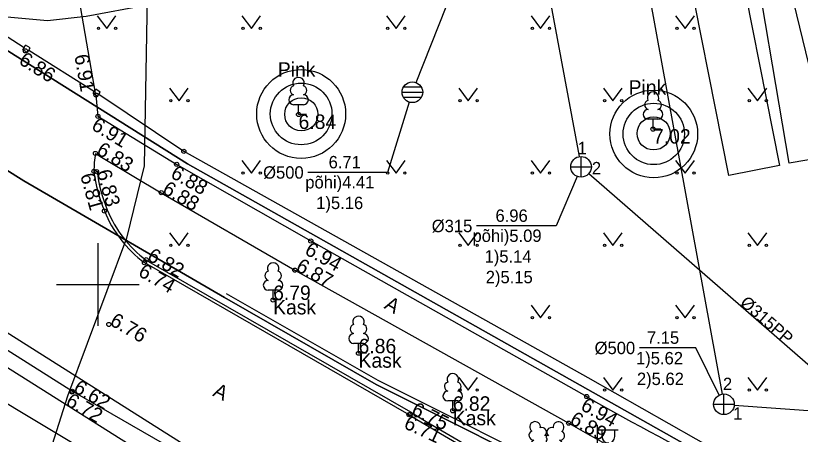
# Model space of a CAD drawing. Extents: x 473307 to 473719, y 6532843 to 6533381.
# Drawn here: x 473546.03 to 473584.01, y 6532942.76 to 6532963.02 of the extents above; entities that cross this region are included whole.
import ezdxf

# ---------------------------------------------------------------- set-up
doc = ezdxf.new("R2010")
doc.units = 0
for name, color, linetype in [('AED', 7, 'Continuous'), ('Default', 7, 'Continuous'), ('HALJASTUS', 7, 'Continuous'), ('KKAEV', 7, 'Continuous'), ('KKAEV_NR', 7, 'Continuous'), ('KORGUS', 7, 'Continuous'), ('KPKAABEL', 7, 'Continuous'), ('KTRASS', 7, 'Continuous'), ('MPKAABEL', 7, 'Continuous'), ('MPOHULIIN', 7, 'Continuous'), ('PIIR', 7, 'Continuous'), ('POST', 7, 'Continuous'), ('PUU', 7, 'Continuous'), ('RAJATIS', 7, 'Continuous'), ('SKKAEV', 7, 'Continuous'), ('SKKAEV_NR', 7, 'Continuous'), ('SKTRASS', 7, 'Continuous'), ('SKTRASS_TEKST', 7, 'Continuous'), ('TEE', 7, 'Continuous'), ('VORK', 7, 'Continuous'), ('VTRASS', 7, 'Continuous')]:
    doc.layers.add(name, color=color, linetype=linetype)

# ---------------------------------------------------------------- blocks, each defined once
blk = doc.blocks.new('KAKAEV')
at = {"layer": 'Default'}
for p, q in [((0, -1), (0, 1)), ((-1, 0), (1, 0))]:
    blk.add_line(p, q, dxfattribs=at)
blk.add_circle((0, 0), 1, dxfattribs=at)
blk = doc.blocks.new('LEHTP1')
at = {"layer": 'Default'}
for p, q in [((0.48, 0.95), (-0.48, 0.95)), ((0, 0), (0, 0.95)), ((0.76, 0), (0, 0))]:
    blk.add_line(p, q, dxfattribs=at)
for centre, radius, start, end in [((0, 3.04), 0.554, 332.5799, 207.4201), ((-0.34, 2.345), 0.465, 109.02174, 253.14154), ((0.34, 2.345), 0.465, 286.85082, 70.98591), ((-0.475, 1.425), 0.475, 90.0016, 269.3953), ((0.475, 1.425), 0.475, 270.6047, 89.9984)]:
    blk.add_arc(centre, radius, start, end, dxfattribs=at)
blk = doc.blocks.new('VAPOST')
at = {"layer": 'Default'}
for p, q in [((0, 0.5), (0, 4.5)), ((0, 4), (2, 4)), ((0.453, 3.358), (0.453, 4)), ((1.679, 3.358), (1.679, 4))]:
    blk.add_line(p, q, dxfattribs=at)
blk.add_arc((1.066, 3.358), 0.613, 180, 0, dxfattribs=at)
blk = doc.blocks.new('LEHTP2')
at = {"layer": 'Default'}
for p, q in [((-0.88, 0.67), (0.01, 1.02)), ((0, 0), (-0.35, 0.88)), ((0, 0), (0.36, 0.88)), ((0.01, 1.02), (0.89, 0.66)), ((0.76, 0), (0, 0))]:
    blk.add_line(p, q, dxfattribs=at)
blk.add_lwpolyline([(0.01, 2.01), (-0.03, 1.86), (-0.03, 1.82), (-0.01, 1.76), (0.03, 1.69), (0.04, 1.65), (0.01, 1.58), (-0.04, 1.48), (-0.05, 1.43), (-0.04, 1.4), (-0.02, 1.34), (0.05, 1.22), (0.06, 1.18), (0.05, 1.14), (0.02, 1.07), (0.01, 1.02)], dxfattribs=at)
for centre, radius, start, end in [((-1.114, 2.828), 0.512, 111.50269, 232.51731), ((-1.114, 2.828), 0.512, 350.48556, 111.50017), ((1.158, 2.811), 0.512, 67.6168, 188.63142), ((1.158, 2.811), 0.512, 306.59966, 67.61428), ((-1.262, 2.005), 0.448, 111.43041, 274.49868), ((-0.445, 2.327), 0.448, 308.50412, 111.57247), ((0.481, 2.318), 0.45, 67.7016, 230.51262), ((1.293, 1.986), 0.448, 264.6183, 67.68657), ((-1.053, 1.117), 0.475, 111.50143, 291.50036), ((0.008, 1.535), 0.475, 66.76552, 111.50149), ((1.07, 1.101), 0.475, 247.61661, 67.61554)]:
    blk.add_arc(centre, radius, start, end, dxfattribs=at)
blk = doc.blocks.new('VARPOS')
at = {"layer": 'Default'}
for p, q in [((-0.25, 0.25), (-0.25, -0.25)), ((-0.25, 0.25), (0.25, 0.25)), ((0.25, 0.25), (0.25, -0.25)), ((-0.25, -0.25), (0.25, -0.25))]:
    blk.add_line(p, q, dxfattribs=at)
blk = doc.blocks.new('REKAEV')
at = {"layer": 'Default'}
for p, q in [((-1, 0), (1, 0)), ((0.86, 0.5), (-0.86, 0.5)), ((0.86, -0.5), (-0.86, -0.5))]:
    blk.add_line(p, q, dxfattribs=at)
blk.add_circle((0, 0), 1, dxfattribs=at)
blk = doc.blocks.new('MURU')
at = {"layer": 'Default'}
for p, q in [((-0.927, 1.213), (0, 0)), ((0, 0), (0.891, 1.213))]:
    blk.add_line(p, q, dxfattribs=at)
for centre in [(-0.802, 0), (0.856, 0)]:
    blk.add_circle(centre, 0.11, dxfattribs=at)
blk = doc.blocks.new('VKORIS')
at = {"layer": 'Default'}
for p, q in [((0, 4), (0, -4)), ((-4, 0), (4, 0))]:
    blk.add_line(p, q, dxfattribs=at)

msp = doc.modelspace()

# ---------------------------------------------------------------- linework, layer by layer
at = {"layer": 'AED'}
for points in [[(473531.197, 6532971.332), (473546.442, 6532961.469)], [(473546.66, 6532961.347), (473549.841, 6532959.348)], [(473550.051, 6532959.211), (473554.174, 6532956.453), (473573.719, 6532945.513), (473580.254, 6532941.8), (473591.86, 6532937.524), (473605.919, 6532932.298), (473608.286, 6532931.42), (473621.231, 6532928.229), (473637.541, 6532925.082), (473652.528, 6532925.143), (473654.3, 6532926.84), (473651.933, 6532941.676), (473648.983, 6532959.55), (473630.652, 6532956.493)]]:
    msp.add_lwpolyline(points, dxfattribs=at)
at = {"layer": 'KKAEV_NR'}
msp.add_lwpolyline([(473580.087, 6532944.655), (473578.944, 6532946.937), (473576.223, 6532946.937)], dxfattribs=at)
at = {"layer": 'KORGUS'}
for centre in [(473546.5, 6532961.312), (473549.913, 6532959.174), (473550.008, 6532958.145), (473559.72, 6532958.233), (473576.879, 6532957.526), (473549.889, 6532956.35), (473554.167, 6532956.453), (473553.823, 6532955.821), (473549.817, 6532955.48), (473549.942, 6532955.467), (473553.076, 6532954.45), (473550.323, 6532953.564), (473560.312, 6532952.113), (473552.344, 6532951.212), (473552.259, 6532951.064), (473559.541, 6532950.703), (473558.489, 6532949.258), (473558.489, 6532949.258), (473550.537, 6532948.074), (473550.537, 6532948.074), (473562.625, 6532946.679), (473562.625, 6532946.679), (473548.754, 6532944.802), (473548.754, 6532944.802), (473548.771, 6532944.84), (473548.771, 6532944.84), (473573.67, 6532944.583), (473565.065, 6532943.709), (473565.065, 6532943.709), (473565.128, 6532943.726), (473565.128, 6532943.726), (473567.185, 6532943.895), (473567.185, 6532943.895), (473572.797, 6532943.295)]:
    msp.add_circle(centre, 0.1, dxfattribs=at)
at = {"layer": 'KPKAABEL'}
msp.add_lwpolyline([(473552.428, 6532965.743), (473552.248, 6532955.743), (473551.396, 6532952.25), (473548.538, 6532944.595), (473546.922, 6532939.52), (473555.37, 6532934.798), (473562.977, 6532930.797), (473573.936, 6532926.157), (473585.002, 6532921.176), (473597.713, 6532916.33), (473608.101, 6532913.364), (473620.133, 6532910.115), (473635.44, 6532908.143), (473647.319, 6532907.126), (473658.175, 6532907.682), (473669.898, 6532907.954), (473678.245, 6532908.166), (473679.837, 6532908.723), (473681.3, 6532908.756), (473682.619, 6532907.437), (473683.14, 6532903.797)], dxfattribs=at)
at = {"layer": 'KTRASS'}
msp.add_line((473505.335, 6532971.329), (473560.125, 6532936.877), dxfattribs=at)
for points in [[(473573.778, 6532980.035), (473580.221, 6532944.7)], [(473580.81, 6532944.172), (473634.611, 6532940.293)]]:
    msp.add_lwpolyline(points, dxfattribs=at)
at = {"layer": 'MPKAABEL'}
for points in [[(473592.161, 6532931.655), (473583.871, 6532934.989), (473574.572, 6532939.314), (473574.03, 6532940.034), (473574.304, 6532941.029), (473573.472, 6532940.172), (473563.473, 6532945.174), (473556.129, 6532949.371), (473546.422, 6532955.029), (473536.136, 6532961.464), (473535.978, 6532962.869), (473534.663, 6532962.568), (473525.661, 6532968.571), (473517.097, 6532975.071), (473509.151, 6532981.519), (473503.051, 6532987.775), (473502.694, 6532988.631), (473501.293, 6532988.874), (473494.528, 6532995.717), (473488.455, 6533001.872), (473481.096, 6533010.082), (473475.299, 6533017.476)], [(473493.252, 6532975.715), (473497.24, 6532978.112), (473498.183, 6532979.06), (473499.269, 6532980.163), (473501.448, 6532982.423), (473503.504, 6532984.545), (473505.843, 6532986.884), (473507.45, 6532987.966), (473517.665, 6532979.32), (473529.752, 6532970.098), (473534.316, 6532966.914), (473541.139, 6532963.364), (473547.56, 6532962.777), (473549.436, 6532962.995), (473552.396, 6532963.548), (473552.501, 6532963.798), (473552.517, 6532963.893), (473552.555, 6532965.764)], [(473583.229, 6532977.274), (473582.388, 6532976.276), (473581.518, 6532974.611), (473581.518, 6532974.611), (473581.55, 6532974.485), (473581.806, 6532974.382), (473582.092, 6532971.765), (473582.897, 6532967.472), (473583.344, 6532967.218), (473583.499, 6532966.399), (473583.498, 6532965.835), (473583.235, 6532965.46), (473587.471, 6532948.068)], [(473535.978, 6532962.869), (473536.136, 6532961.464), (473546.422, 6532955.029), (473556.129, 6532949.371), (473563.473, 6532945.174), (473573.472, 6532940.172), (473574.304, 6532941.029)], [(473574.304, 6532941.029), (473573.428, 6532940.429), (473563.572, 6532945.359), (473556.234, 6532949.553)]]:
    msp.add_lwpolyline(points, dxfattribs=at)
at = {"layer": 'MPOHULIIN'}
msp.add_lwpolyline([(473423.194, 6533272.897), (473391.791, 6533270.484), (473361.09, 6533267.919), (473364.229, 6533220.925), (473380.477, 6533175.317), (473396.165, 6533131.758), (473413.567, 6533083.532), (473430.968, 6533052.6), (473459.84, 6533016.944), (473493.252, 6532975.715), (473524.159, 6532957.128), (473561.498, 6532934.712), (473599.705, 6532914.54), (473648.184, 6532910.183)], dxfattribs=at)
at = {"layer": 'PIIR'}
msp.add_lwpolyline([(473486.57, 6533007.64), (473478.82, 6533017), (473548.5, 6533028.91), (473572.63, 6533056.43), (473618.6, 6533063.82), (473630.89, 6533065.72), (473654.16, 6532926.37), (473652.82, 6532924.82), (473637.7, 6532924.6), (473625.07, 6532926.73), (473607.63, 6532930.98), (473579.04, 6532941.93), (473554.34, 6532955.84), (473531.51, 6532970.21), (473509.62, 6532987.09)], close=True, dxfattribs=at)
msp.add_lwpolyline([(473455.33, 6533045.76), (473478.82, 6533017), (473486.57, 6533007.64), (473509.62, 6532987.09), (473531.51, 6532970.21), (473554.34, 6532955.84), (473579.04, 6532941.93), (473607.63, 6532930.98), (473625.07, 6532926.73), (473637.7, 6532924.6), (473652.82, 6532924.82), (473654.16, 6532926.37), (473664.64, 6532927.81), (473668.24, 6532906.4), (473641.69, 6532906.33), (473620.6, 6532909.02), (473600.1, 6532914.5), (473579.89, 6532922.16), (473559.95, 6532931.3), (473540.88, 6532942.28), (473521.95, 6532954.78), (473501.05, 6532969.5), (473492.55, 6532977.62), (473473.12, 6532997.79)], dxfattribs=at)
at = {"layer": 'RAJATIS'}
for centre, radius in [((473559.846, 6532958.26), 2.151), ((473559.846, 6532958.26), 1.492), ((473576.915, 6532957.292), 2.122), ((473559.853, 6532958.242), 0.804), ((473576.915, 6532957.292), 1.485), ((473576.909, 6532957.317), 0.8)]:
    msp.add_circle(centre, radius, dxfattribs=at)
at = {"layer": 'SKKAEV_NR'}
for points in [[(473565.081, 6532958.833), (473564.031, 6532955.428), (473560.176, 6532955.428)], [(473573.2, 6532955.241), (473572.195, 6532952.839), (473568.34, 6532952.839)]]:
    msp.add_lwpolyline(points, dxfattribs=at)
at = {"layer": 'SKTRASS'}
for points in [[(473565.412, 6532959.776), (473570.144, 6532971.727)], [(473570.419, 6532971.7), (473573.302, 6532956.194)], [(473573.77, 6532955.374), (473585.614, 6532945.077)]]:
    msp.add_lwpolyline(points, dxfattribs=at)
at = {"layer": 'TEE'}
msp.add_line((473549.686, 6532956.116), (473549.686, 6532956.116), dxfattribs=at)
for points in [[(473507.269, 6532973.243), (473516.735, 6532966.211), (473521.977, 6532962.129), (473526.063, 6532959.019), (473526.41, 6532958.663), (473523.968, 6532954.435), (473525.686, 6532952.96), (473528.95, 6532956.691), (473529.581, 6532956.846), (473534.188, 6532954.059), (473548.771, 6532944.84), (473558.935, 6532938.993), (473557.576, 6532936.09)], [(473549.913, 6532959.174), (473548.867, 6532965.152)], [(473549.913, 6532959.174), (473550.008, 6532958.145), (473553.823, 6532955.821), (473560.312, 6532952.113), (473573.67, 6532944.583)], [(473549.889, 6532956.35), (473550.345, 6532956.077), (473553.076, 6532954.45), (473559.541, 6532950.703), (473572.797, 6532943.295)], [(473552.259, 6532951.064), (473565.065, 6532943.709)], [(473552.341, 6532951.19), (473565.141, 6532943.838)]]:
    msp.add_lwpolyline(points, dxfattribs=at)
for centre, radius, start, end in [((473554.404, 6532955.538), 4.587, 169.8089, 180.7293), ((473556.992, 6532956.35), 7.228, 186.9144, 202.6728), ((473556.992, 6532956.35), 7.078, 186.9144, 202.6792), ((473555.741, 6532955.76), 5.697, 202.0573, 233.3555), ((473555.741, 6532955.76), 5.847, 202.0653, 233.4431), ((473627.25, 6533037.149), 106.955, 239.93646, 244.18867), ((473649.986, 6533084.531), 164.445, 238.90844, 243.87641), ((473649.986, 6533084.531), 164.295, 238.90789, 243.87579), ((473627.795, 6533039.271), 110.617, 240.18538, 244.53648)]:
    msp.add_arc(centre, radius, start, end, dxfattribs=at)
at = {"layer": 'VTRASS'}
msp.add_lwpolyline([(473503.731, 6532976.927), (473535.265, 6532954.21), (473555.891, 6532941.175), (473565.122, 6532936.508), (473600.672, 6532921.587), (473636.512, 6532914.617), (473674.923, 6532915.363), (473675.557, 6532915.427)], dxfattribs=at)
for points in [[(473585.934, 6532956.295), (473583.47, 6532955.877), (473581.516, 6532967.408), (473583.98, 6532967.826)], [(473580.727, 6532967.275), (473582.995, 6532955.767), (473580.543, 6532955.283), (473578.275, 6532966.791)]]:
    msp.add_lwpolyline(points, close=True, dxfattribs=at)

# ---------------------------------------------------------------- block references
at = {"layer": 'AED', "xscale": 0.5}
for p, yscale, rotation in [((473546.553, 6532961.411), 0.5, 148.96420870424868), ((473549.947, 6532959.281), 0.49999999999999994, 147.720314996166)]:
    msp.add_blockref('VARPOS', p, dxfattribs=dict(at, yscale=yscale, rotation=rotation))
at = {"layer": 'HALJASTUS', "xscale": 0.5, "yscale": 0.5}
for p in [(473550.438, 6532962.399), (473557.438, 6532962.399), (473564.438, 6532962.399), (473571.438, 6532962.399), (473578.438, 6532962.399), (473553.938, 6532958.899), (473567.938, 6532958.899), (473574.938, 6532958.899), (473581.938, 6532958.899), (473557.438, 6532955.399), (473564.438, 6532955.399), (473571.438, 6532955.399), (473578.438, 6532955.399), (473553.938, 6532951.899), (473567.938, 6532951.899), (473574.938, 6532951.899), (473581.938, 6532951.899), (473571.438, 6532948.399), (473578.438, 6532948.399), (473567.938, 6532944.899), (473574.938, 6532944.899), (473581.938, 6532944.899)]:
    msp.add_blockref('MURU', p, dxfattribs=at)
at = {"layer": 'KKAEV', "xscale": 0.5, "yscale": 0.5}
msp.add_blockref('KAKAEV', (473580.311, 6532944.208), dxfattribs=at)
at = {"layer": 'POST', "xscale": 0.5, "yscale": 0.5}
msp.add_blockref('VAPOST', (473574.186, 6532940.966), dxfattribs=at)
at = {"layer": 'PUU', "xscale": 0.5, "yscale": 0.5}
for name, p in [('LEHTP1', (473559.72, 6532958.233)), ('LEHTP1', (473576.879, 6532957.526)), ('LEHTP1', (473558.489, 6532949.258)), ('LEHTP1', (473562.625, 6532946.679)), ('LEHTP1', (473567.185, 6532943.895)), ('LEHTP2', (473571.726, 6532941.7))]:
    msp.add_blockref(name, p, dxfattribs=at)
at = {"layer": 'SKKAEV', "xscale": 0.5, "yscale": 0.5}
for name, p in [('REKAEV', (473565.228, 6532959.311)), ('KAKAEV', (473573.393, 6532955.702))]:
    msp.add_blockref(name, p, dxfattribs=at)
at = {"layer": 'VORK', "xscale": 0.5, "yscale": 0.5}
msp.add_blockref('VKORIS', (473550, 6532950), dxfattribs=at)

# ---------------------------------------------------------------- texts
at = {"layer": 'KKAEV_NR'}
for s, p in [('7.15', (473576.583, 6532947.137)), ('%%C500', (473574.051, 6532946.637)), ('1)5.62', (473576.055, 6532946.141)), ('2)5.62', (473576.098, 6532945.141)), ('2', (473580.262, 6532944.896)), ('1', (473580.759, 6532943.462))]:
    msp.add_text(s, height=0.6, dxfattribs=at).set_placement(p)
at = {"layer": 'KORGUS'}
for s, rotation, p in [('6.86', 327.8583, (473546.128, 6532960.719)), ('6.91', 279.9249, (473548.867, 6532961.089)), ('6.91', 328.6513, (473549.644, 6532957.547)), ('6.83', 329.1461, (473549.889, 6532956.35)), ('6.83', 285.714, (473549.942, 6532955.467)), ('6.88', 330.2551, (473553.476, 6532955.213)), ('6.81', 285.714, (473549.143, 6532955.29)), ('6.88', 329.9042, (473553.076, 6532954.45)), ('6.82', 330.1968, (473552.344, 6532951.212)), ('6.94', 330.5897, (473559.968, 6532951.503)), ('6.74', 330.1968, (473551.911, 6532950.457)), ('6.87', 330.8017, (473559.541, 6532950.703)), ('6.76', 329.897, (473550.537, 6532948.074)), ('6.62', 329.7497, (473548.771, 6532944.84)), ('6.72', 329.7497, (473548.401, 6532944.197)), ('6.94', 330.5157, (473573.325, 6532943.974)), ('6.75', 333.8392, (473565.128, 6532943.726)), ('6.89', 330.7726, (473572.797, 6532943.295)), ('6.71', 335.0102, (473564.769, 6532943.075))]:
    msp.add_text(s, height=0.7, rotation=rotation, dxfattribs=at).set_placement(p)
for s, p in [('6.84', (473559.72, 6532957.533)), ('7.02', (473576.879, 6532956.826)), ('6.79', (473558.489, 6532949.258)), ('6.86', (473562.625, 6532946.679)), ('6.82', (473567.185, 6532943.895))]:
    msp.add_text(s, height=0.7, dxfattribs=at).set_placement(p)
at = {"layer": 'PUU'}
for p in [(473558.489, 6532948.558), (473562.625, 6532945.979), (473567.185, 6532943.195)]:
    msp.add_text('Kask', height=0.7, dxfattribs=at).set_placement(p)
at = {"layer": 'RAJATIS'}
for p in [(473558.716, 6532960.062), (473575.696, 6532959.194)]:
    msp.add_text('Pink', height=0.7, dxfattribs=at).set_placement(p)
at = {"layer": 'SKKAEV_NR'}
for s, p in [('1', (473573.229, 6532956.311)), ('6.71', (473561.175, 6532955.628)), ('2', (473573.918, 6532955.337)), ('%%C500', (473558.005, 6532955.128)), ('põhi)4.41', (473560.046, 6532954.656)), ('1)5.16', (473560.575, 6532953.656)), ('6.96', (473569.253, 6532953.039)), ('%%C315', (473566.168, 6532952.539)), ('põhi)5.09', (473568.139, 6532952.067)), ('1)5.14', (473568.725, 6532951.067)), ('2)5.15', (473568.782, 6532950.067))]:
    msp.add_text(s, height=0.6, dxfattribs=at).set_placement(p)
at = {"layer": 'SKTRASS_TEKST'}
msp.add_text('%%C315PP', height=0.6, rotation=318.9955, dxfattribs=at).set_placement((473581.045, 6532949.049))
at = {"layer": 'TEE'}
for rotation, p in [(329.9712, (473563.822, 6532948.878)), (334.1331, (473555.526, 6532944.639))]:
    msp.add_text('A', height=0.7, rotation=rotation, dxfattribs=at).set_placement(p)

doc.saveas('drawing.dxf')
